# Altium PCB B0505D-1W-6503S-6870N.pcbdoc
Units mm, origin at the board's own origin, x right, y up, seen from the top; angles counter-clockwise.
Board outline 42 x 16 mm, 2 copper layers (Top Layer, Bottom Layer), stack 0.78 mm thick; 14 components, 9 nets, 37 pads, 7 vias.
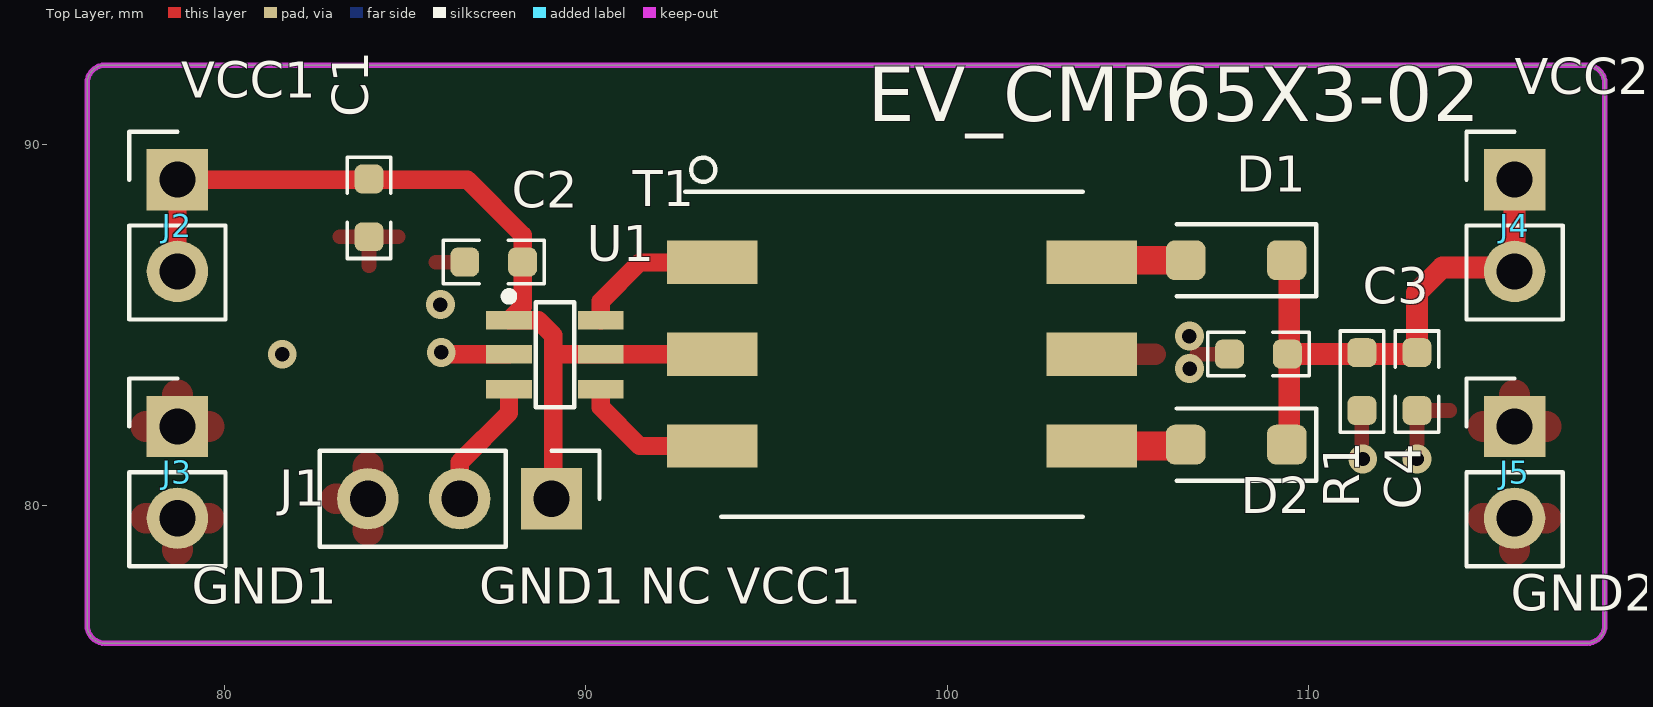
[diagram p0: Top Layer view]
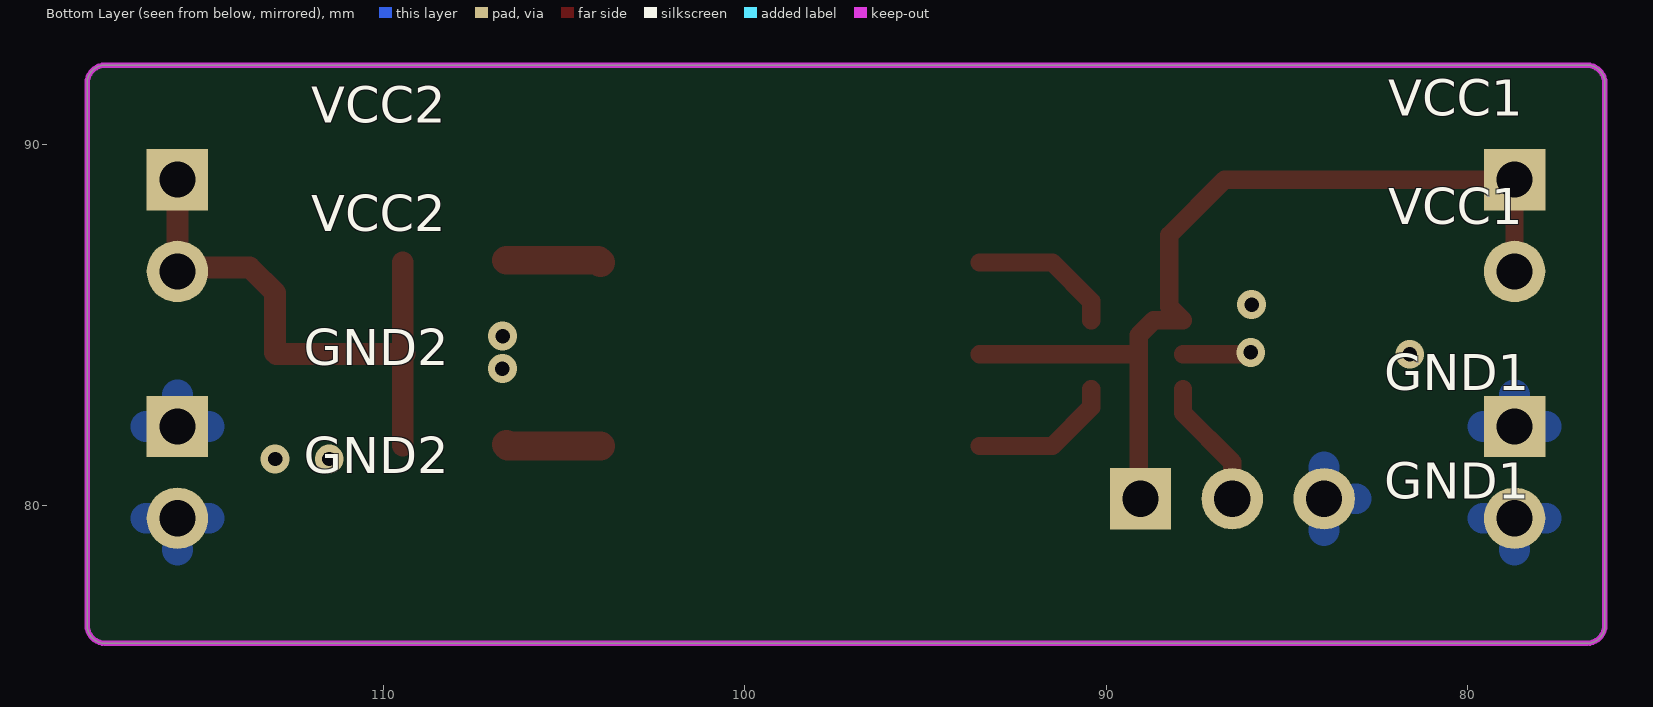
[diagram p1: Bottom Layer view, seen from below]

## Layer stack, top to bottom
Top Solder Mask Layer: solder mask 0.01, Dk 0
Top Layer: signal copper 0.035
dielectric 1: surface 0.71, FR4, Dk 4.5
Bottom Layer: signal copper 0.035
Bottom Solder Mask Layer: solder mask 0.01, Dk 0

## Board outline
76.7,76.2 117.7,76.2 ccw(c117.7,76.7) 118.2,76.7 118.2,91.7 ccw(c117.7,91.7) 117.7,92.2 76.7,92.2 ccw(c76.7,91.7) 76.2,91.7 76.2,76.7 ccw(c76.7,76.7)

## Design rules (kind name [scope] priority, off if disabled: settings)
BoardOutlineClearance safeClearance [All] p0: genericclearance=0.254 ignorepadtopadclearanceinfootprint=FALSE except(0: Arc-SplitContinuation Track-SplitContinuation SMDPad-SplitContinuation THPad-SplitContinuation Via-SplitContinuation Fill-SplitContinuation Poly-SplitContinuation Region-SplitContinuation Text-SplitContinuation)
BoardOutlineClearance Plane_innerPlane [All] p0: genericclearance=0.254 ignorepadtopadclearanceinfootprint=FALSE except(0: Arc-SplitContinuation Track-SplitContinuation SMDPad-SplitContinuation THPad-SplitContinuation Via-SplitContinuation Fill-SplitContinuation Poly-SplitContinuation Region-SplitContinuation Text-SplitContinuation)
BoardOutlineClearance Copper_CopperRegion [All] p0: genericclearance=0.254 ignorepadtopadclearanceinfootprint=FALSE except(0: Arc-SplitContinuation Track-SplitContinuation SMDPad-SplitContinuation THPad-SplitContinuation Via-SplitContinuation Fill-SplitContinuation Poly-SplitContinuation Region-SplitContinuation Text-SplitContinuation)
BoardOutlineClearance Copper_CopperRegion1 [All] p0: genericclearance=0.254 ignorepadtopadclearanceinfootprint=FALSE except(0: Arc-SplitContinuation Track-SplitContinuation SMDPad-SplitContinuation THPad-SplitContinuation Via-SplitContinuation Fill-SplitContinuation Poly-SplitContinuation Region-SplitContinuation Text-SplitContinuation)
BoardOutlineClearance Copper_CopperRegion2 [All] p0: genericclearance=0.254 ignorepadtopadclearanceinfootprint=FALSE except(0: Arc-SplitContinuation Track-SplitContinuation SMDPad-SplitContinuation THPad-SplitContinuation Via-SplitContinuation Fill-SplitContinuation Poly-SplitContinuation Region-SplitContinuation Text-SplitContinuation)
BoardOutlineClearance Copper_CopperRegion3 [All] p0: genericclearance=0.254 ignorepadtopadclearanceinfootprint=FALSE except(0: Arc-SplitContinuation Track-SplitContinuation SMDPad-SplitContinuation THPad-SplitContinuation Via-SplitContinuation Fill-SplitContinuation Poly-SplitContinuation Region-SplitContinuation Text-SplitContinuation)
BoardOutlineClearance Copper_CopperRegion4 [All] p0: genericclearance=0.254 ignorepadtopadclearanceinfootprint=FALSE except(0: Arc-SplitContinuation Track-SplitContinuation SMDPad-SplitContinuation THPad-SplitContinuation Via-SplitContinuation Fill-SplitContinuation Poly-SplitContinuation Region-SplitContinuation Text-SplitContinuation)
BoardOutlineClearance otherClearance [All] p0: genericclearance=0.254 ignorepadtopadclearanceinfootprint=FALSE except(0: Arc-SplitContinuation Track-SplitContinuation SMDPad-SplitContinuation THPad-SplitContinuation Via-SplitContinuation Fill-SplitContinuation Poly-SplitContinuation Region-SplitContinuation Text-SplitContinuation)
Clearance safeClearance [All] p1: gap=0.178 ignorepadtopadclearanceinfootprint=FALSE
Clearance Plane_innerPlane [All] p1: gap=0.178 ignorepadtopadclearanceinfootprint=FALSE
Clearance Copper_CopperRegion [All] p1: gap=0.178 ignorepadtopadclearanceinfootprint=FALSE
Clearance Copper_CopperRegion1 [All] p1: gap=0.178 ignorepadtopadclearanceinfootprint=FALSE
Clearance Copper_CopperRegion2 [All] p1: gap=0.178 ignorepadtopadclearanceinfootprint=FALSE
Clearance Copper_CopperRegion3 [All] p1: gap=0.178 ignorepadtopadclearanceinfootprint=FALSE
Clearance Copper_CopperRegion4 [All] p1: gap=0.178 ignorepadtopadclearanceinfootprint=FALSE
Clearance otherClearance [All] p1: gap=0.178 ignorepadtopadclearanceinfootprint=FALSE
DiffPairsRouting differentialPair [All] p1: maxuncoupledlength=10 minlimit=6 maxlimit=Infinity mostfreqgap=6 toplayer_minwidth=5 toplayer_prefwidth=10 toplayer_maxwidth=100 bottomlayer_minwidth=5 bottomlayer_prefwidth=10 bottomlayer_maxwidth=100
PasteMaskExpansion Common [All] p1: expansion=0
PlaneConnect innerPlane [All] p1: planeconnectstyle=Relief reliefexpansion=0.508 reliefentries=4 reliefconductorwidth=0.254 reliefairgap=0.254
PolygonConnect CopperRegion [All] p1: connectstyle=Relief reliefentries=4 reliefconductorwidth=0 polygonreliefangle="90 Angle" airgapwidth=1
PolygonConnect CopperRegion1 [All] p1: connectstyle=Relief reliefentries=4 reliefconductorwidth=0 polygonreliefangle="90 Angle" airgapwidth=1
PolygonConnect CopperRegion2 [All] p1: connectstyle=Relief reliefentries=4 reliefconductorwidth=0 polygonreliefangle="90 Angle" airgapwidth=1
PolygonConnect CopperRegion3 [All] p1: connectstyle=Relief reliefentries=4 reliefconductorwidth=0 polygonreliefangle="90 Angle" airgapwidth=1
PolygonConnect CopperRegion4 [All] p1: connectstyle=Relief reliefentries=4 reliefconductorwidth=0 polygonreliefangle="90 Angle" airgapwidth=1
RoutingVias viaSize [All] p1: viastyle="Through Hole" holewidth=12.0078 minholewidth=11.811 maxholewidth=236.2204 width=12.0078 minwidth=11.811 maxwidth=236.2204
SolderMaskExpansion Common [All] p1: useseparateexpansions=TRUE expansion=0 expansionbottom=0
Width trackWidth [All] p1: maxlimit=100 minlimit=5 preferedwidth=10

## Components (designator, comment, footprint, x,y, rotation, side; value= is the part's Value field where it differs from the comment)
C1 "1uF" MYLibrary:C0603 84,88.25 r90 top
C2 "1uF" MYLibrary:C0603 87.45,86.75 r0 top
C3 "4.7uF" MYLibrary:C0603 108.614,84.204 r0 top
C4 "0.1uF" MYLibrary:C0603 113,83.442 r90 top
D1 "B0540WS" Diode_SMD:D_SOD-123F 108,86.8 r180 top
D2 "B0540WS" Diode_SMD:D_SOD-123F 108,81.7 r180 top
J1 "Conn_01x03" Connector_PinHeader_2.54mm:PinHeader_1x03_P2.54mm_Vertical 89.05,80.2 r270 top
J2 "Conn_01x02" Connector_PinHeader_2.54mm:PinHeader_1x02_P2.54mm_Vertical 78.7,89.03 r0 top
J3 "Conn_01x02" Connector_PinHeader_2.54mm:PinHeader_1x02_P2.54mm_Vertical 78.7,82.2 r0 top
J4 "Conn_01x02" Connector_PinHeader_2.54mm:PinHeader_1x02_P2.54mm_Vertical 115.7,89.03 r0 top
J5 "Conn_01x02" Connector_PinHeader_2.54mm:PinHeader_1x02_P2.54mm_Vertical 115.7,82.2 r0 top
R1 "5.1K" MYLibrary:R0603 111.476,83.442 r270 top
T1 "CMT78F0N" MYLibrary:SMD-6W 98.748,84.2 r0 top
U1 "CMP65X3S" MYLibrary:SOT23-6 89.144,84.2 r0 top

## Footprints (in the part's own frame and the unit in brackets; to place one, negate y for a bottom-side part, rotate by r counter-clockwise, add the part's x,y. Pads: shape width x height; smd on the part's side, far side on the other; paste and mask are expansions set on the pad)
Connector_PinHeader_2.54mm:PinHeader_1x02_P2.54mm_Vertical [mm]
  rect 1.7x1.7 hole 1: 1(0,0)
  round 1.7 hole 1: 2(0,-2.54)
  silkscreen extent -1.33,-3.87 1.33,1.33
Connector_PinHeader_2.54mm:PinHeader_1x03_P2.54mm_Vertical [mm]
  rect 1.7x1.7 hole 1: 1(0,0)
  round 1.7 hole 1: 2(0,-2.54) 3(0,-5.08)
  silkscreen extent -1.33,-6.41 1.33,1.33
Diode_SMD:D_SOD-123F [mm]
  rrect45% 1.1x1.1 smd: 1(-1.4,0) 2(1.4,0)
  silkscreen extent -2.21,-1 1.65,1
MYLibrary:C0603 [mm]
  rrect50% 0.8x0.8 smd: 1(-0.8,0) 2(0.8,0)
  silkscreen extent -1.4,-0.6 1.4,0.6
MYLibrary:R0603 [mm]
  rrect50% 0.8x0.8 smd: 1(-0.8,0) 2(0.8,0)
  silkscreen extent -1.4,-0.6 1.4,0.6
MYLibrary:SMD-6W [mm]
  rect 2.5x1.2 smd: 1(-5.25,2.54) 2(-5.25,0) 3(-5.25,-2.54) 4(5.25,-2.54) 5(5.25,0) 6(5.25,2.54)
  silkscreen extent -6,-4.5 5,5.44
MYLibrary:SOT23-6 [mil]
  rect 50x20 smd: 1(-50,37) 2(-50,0) 3(-50,-38) 4(50,-38) 5(50,0) 6(50,37)
  silkscreen extent -54,-58 21,67

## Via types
v1: diameter 0.8, hole 0.4, Top Layer to Bottom Layer, 7 vias

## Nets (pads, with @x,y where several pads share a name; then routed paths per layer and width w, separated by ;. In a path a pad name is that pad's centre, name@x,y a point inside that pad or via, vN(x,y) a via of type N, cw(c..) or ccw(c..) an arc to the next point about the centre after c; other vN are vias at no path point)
GND1: C1.1 C2.1 J1.3 J3.1 J3.2 U1.2 | length 1.9
  Top Layer w0.508: v1(86,84.25) 86.05,84.2 U1.2
  other v1: 81.6,84.2 85.975,85.575
GND2: C3.1 C4.1 J5.1 J5.2 R1.2 T1.5
  other v1: 111.5,81.3 113,81.3 106.709,83.8 106.7,84.7
NET-(D1-A): D1.2 T1.6 | length 2.6
  Top Layer w0.8: T1.6 104.058,86.8 D1.2
NET-(D2-A): D2.2 T1.4 | length 2.6
  Top Layer w0.8: T1.4 106.56,81.66 D2.2
NET-(U1-VD1): T1.1 U1.6 | length 4.1
  Top Layer w0.508: U1.6 90.414,85.664 91.49,86.74 T1.1
NET-(U1-VD2): T1.3 U1.4 | length 4
  Top Layer w0.508: U1.4 90.414,82.736 91.49,81.66 T1.3
SEL: J1.2 U1.3 | length 3.6
  Top Layer w0.508: J1.2 86.51,81.21 87.874,82.574 U1.3
VCC1: C1.2 C2.2 J1.1 J2.1 J2.2 T1.2 U1.1 U1.5 | length 26.1
  Top Layer w0.508: J2.2@78.7,86.302 78.7,87.734 J2.1@78.7,88.842 ; J2.1 86.72,89.03 88.25,87.5 C2.2 88.25,85.516 U1.1 88.685,85.14 89.1,84.725 ; J1.1 89.1,80.25 89.1,84.725 ; T1.2 89.15,84.2 89.1,84.25 89.1,84.725
VCC2: C3.2 C4.2 D1.1 D2.1 J4.1 J4.2 R1.1 | length 15.9
  Top Layer w0.6: C3.2 C4.2@112.962,84.204 ; D2.1@109.466,81.664 D1.1@109.466,86.744 ; C4.2 113,85.9 113.7,86.6 115.59,86.6 J4.2 J4.1

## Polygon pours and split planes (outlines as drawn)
GND1 on Top Layer (solid, remove dead copper, pour order 0): 86.875,87.9 86.875,82.025 86.5,82.025 86.5,76.2 76.2,76.2 76.2,84 80.5,84 80.6,84.1 80.6,86.1 80.6,87.9 84.25,87.9
GND1 on Bottom Layer (solid, remove dead copper, pour order 6): 96.2,76.2 76.2,76.2 76.2,92.2 96.2,92.2
GND2 on Top Layer (solid, remove dead copper, pour order 2): 108.214,83.304 106.35,83.304 106.35,83.3 106.064,83.604 103.564,83.604 103.514,84.804 106.014,84.804 106.25,85.2 106.25,85.204 108.214,85.204
GND2 on Top Layer (solid, remove dead copper, pour order 4): 118.2,76.2 110.8,76.2 110.8,83.1 113.9,83.1 114.1,83.4 114.1,84.2 118.2,84.2
GND2 on Bottom Layer (solid, remove dead copper, pour order 8): 118.2,76.2 102.55,76.25 102.55,92.25 118.2,92.2

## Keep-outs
Board Outline Layer:
  the board outline again, w0.15

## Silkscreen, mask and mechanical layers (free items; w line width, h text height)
Top Silkscreen Layer:
  text "VCC2" at 115.7,91.4 h1
  text "VCC1" at 78.8,91.3 h1
  text "EV_CMP65X3-02" at 97.8,90.65 h1.5
  text "GND1" at 79.1,77.3 h1
  text "GND1 NC VCC1" at 87.05,77.3 h1
  text "GND2" at 115.6,77.1 h1
Bottom Silkscreen Layer:
  text "VCC1 /  / VCC1" at 82.2,87.8 h1
  text "VCC2 /  / VCC2" at 112,87.6 h1
  text "GND2 /  / GND2" at 112.2,80.9 h1
  text "GND1 /  / GND1" at 82.3,80.2 h1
